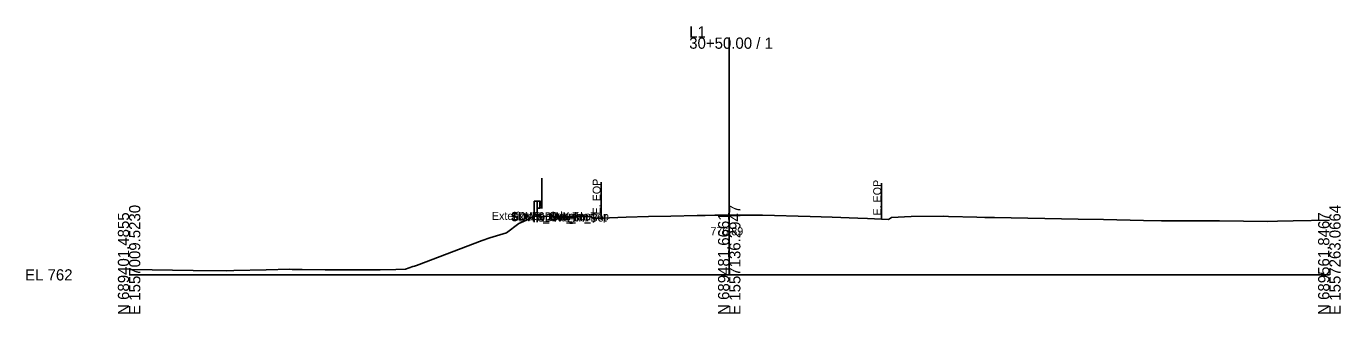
# Model space of a CAD drawing. Extents: x -26 to 2603, y -3010 to 9589.
# Drawn here: x 974.3 to 1302.8, y 3990.3 to 4062.1 of the extents above; entities that cross this region are included whole.
import ezdxf

# ---------------------------------------------------------------- set-up
doc = ezdxf.new("R2010")
doc.units = 0
for name, color, linetype in [('Default', 7, 'Continuous'), ('Exist Cross Section Cell', 7, 'Continuous'), ('Exist XS Center Line Elevation Label', 7, 'Continuous'), ('Exist XS Ground Line', 7, 'Continuous'), ('Prop CMT Conc Surface', 7, 'Continuous'), ('Prop CMT Concrete Structures', 7, 'Continuous'), ('Prop CMT Slope Grass', 7, 'Continuous'), ('Prop XS Earthwork Shape', 7, 'Continuous'), ('Prop XS Label Text', 7, 'Continuous'), ('Scratch_Level_1', 7, 'Continuous'), ('Typical Guardrail CELL', 7, 'Continuous')]:
    doc.layers.add(name, color=color, linetype=linetype)

msp = doc.modelspace()

# ---------------------------------------------------------------- linework, layer by layer
at = {"layer": 'Exist Cross Section Cell'}
for p, q in [((1150, 4000), (1150, 4059.27)), ((1000, 4000), (1150, 4000)), ((1150, 4000), (1300, 4000))]:
    msp.add_line(p, q, dxfattribs=at)
at = {"layer": 'Exist XS Ground Line'}
msp.add_lwpolyline([(1000, 4001.35), (1000.58, 4001.33), (1016.03, 4001.11), (1024.26, 4001.03), (1026.2, 4001.07), (1034.24, 4001.23), (1040.22, 4001.41), (1040.77, 4001.38), (1043.26, 4001.35), (1049.05, 4001.22), (1062.72, 4001.27), (1066.68, 4001.33), (1069.11, 4001.43), (1070.92, 4002.09), (1071.31, 4002.16), (1071.86, 4002.35), (1088.28, 4008.58), (1090.13, 4009.27), (1094.36, 4010.48), (1097.39, 4012.79), (1099.89, 4013.92), (1101.41, 4014.72), (1102.64, 4014.7), (1107.54, 4014.55), (1111.1, 4014.63), (1114.12, 4014.65), (1115.45, 4014.52), (1115.77, 4014.29), (1116.09, 4014.08), (1116.94, 4014.13), (1117.97, 4014.18), (1124.24, 4014.39), (1129.86, 4014.57), (1135.4, 4014.68), (1141.97, 4014.81), (1144.02, 4014.84), (1146.37, 4014.88), (1149.1, 4014.88), (1150, 4014.89), (1151.9, 4014.91), (1158.32, 4014.89), (1170.24, 4014.56), (1175.72, 4014.4), (1182.18, 4014.15), (1184.6, 4014.05), (1188.1, 4013.9), (1189.82, 4013.81), (1190.56, 4014.3), (1195.44, 4014.61), (1203.44, 4014.68), (1204.81, 4014.61), (1211.92, 4014.42), (1213.89, 4014.36), (1216.27, 4014.29), (1237.23, 4013.9), (1243.54, 4013.83), (1253.52, 4013.6), (1258.04, 4013.52), (1260.89, 4013.51), (1272.53, 4013.48), (1284.56, 4013.37), (1287.04, 4013.38), (1290.97, 4013.46), (1300, 4013.67)], dxfattribs=at)
at = {"layer": 'Prop CMT Conc Surface'}
msp.add_line((1111.54, 4014.55), (1106.54, 4014.6), dxfattribs=at)
at = {"layer": 'Prop CMT Concrete Structures'}
msp.add_line((1111.54, 4014.22), (1106.54, 4014.26), dxfattribs=at)
for points in [[(1106.54, 4014.26), (1106.54, 4014.6)], [(1111.54, 4014.55), (1111.54, 4014.22)]]:
    msp.add_lwpolyline(points, dxfattribs=at)
at = {"layer": 'Prop CMT Slope Grass'}
for p, q in [((1106.54, 4014.6), (1105.77, 4014.6)), ((1111.54, 4014.55), (1115.45, 4014.52))]:
    msp.add_line(p, q, dxfattribs=at)
at = {"layer": 'Prop XS Earthwork Shape'}
for points in [[(1105.77, 4014.6), (1106.54, 4014.58), (1106.54, 4014.6)], [(1106.54, 4014.58), (1107.54, 4014.55), (1108.82, 4014.58), (1111.54, 4014.55), (1111.54, 4014.22), (1106.54, 4014.26)], [(1108.82, 4014.58), (1111.1, 4014.63), (1114.12, 4014.65), (1115.45, 4014.52), (1111.54, 4014.55)]]:
    msp.add_lwpolyline(points, close=True, dxfattribs=at)
at = {"layer": 'Prop XS Label Text'}
for p, q in [((1117.97, 4023.18), (1117.97, 4014.18)), ((1188.1, 4022.9), (1188.1, 4013.9))]:
    msp.add_line(p, q, dxfattribs=at)
at = {"layer": 'Scratch_Level_1'}
msp.add_line((1103.19, 4016.6), (1103.19, 4024.11), dxfattribs=at)
at = {"layer": 'Typical Guardrail CELL'}
for p, q in [((1101.96, 4018.43), (1101.21, 4018.43)), ((1101.21, 4018.43), (1101.21, 4014.7)), ((1101.96, 4018.43), (1101.96, 4014.7)), ((1101.96, 4018.43), (1102.7, 4018.43)), ((1102.7, 4018.43), (1102.7, 4016.69)), ((1102.7, 4018.43), (1103.14, 4018.12)), ((1101.96, 4014.7), (1101.21, 4014.7)), ((1101.21, 4014.7), (1101.21, 4013.19)), ((1101.96, 4016.69), (1102.7, 4016.69)), ((1101.96, 4014.7), (1101.96, 4013.19)), ((1102.7, 4017.63), (1103.14, 4017.93)), ((1102.7, 4017.56), (1102.7, 4017.63)), ((1102.7, 4017.56), (1102.7, 4017.49)), ((1102.7, 4017.49), (1103.14, 4017.18)), ((1102.7, 4016.69), (1103.14, 4016.99))]:
    msp.add_line(p, q, dxfattribs=at)
for centre, start, end in [((1103.07, 4018.03), 304.9888, 54.997), ((1103.07, 4017.09), 304.9634, 54.9941)]:
    msp.add_arc(centre, 0.116, start, end, dxfattribs=at)

# ---------------------------------------------------------------- texts
at = {"layer": 'Default'}
for s, height, p in [('Exterior Boundary', 2, (1090.68, 4013.73)), ('SDWK_Out_Top', 2, (1095.47, 4013.73)), ('SDWK_Out_Bot', 2, (1095.5, 4013.4)), ('Exterior Boundary', 2, (1095.68, 4013.63)), ('SDWK_In_Top', 2, (1102.09, 4013.63)), ('SDWK_In_Bot', 2, (1102.12, 4013.3)), ('-', 0.0001, (1000, 4000))]:
    msp.add_text(s, height=height, dxfattribs=at).set_placement(p)
at = {"layer": 'Exist Cross Section Cell'}
for s, p in [('L1', (1140, 4059.27)), ('30+50.00 / 1', (1140, 4056.47)), ('EL 762', (974, 3998.6))]:
    msp.add_text(s, height=2.8, dxfattribs=at).set_placement(p)
for s, p in [('N 689401.4855', (1000, 3990)), ('E 1557009.5230', (1002.8, 3990)), ('N 689481.6661', (1150, 3990)), ('E 1557136.2947', (1152.8, 3990)), ('N 689561.8467', (1300, 3990)), ('E 1557263.0664', (1302.8, 3990))]:
    msp.add_text(s, height=2.8, rotation=90, dxfattribs=at).set_placement(p)
at = {"layer": 'Exist XS Center Line Elevation Label'}
msp.add_text('776.89', height=2, dxfattribs=at).set_placement((1145.31, 4009.89))
at = {"layer": 'Prop XS Label Text'}
for p in [(1117.87, 4015.1), (1188, 4014.82)]:
    msp.add_text('E. EOP', height=2, rotation=90, dxfattribs=at).set_placement(p)

doc.saveas('drawing.dxf')
